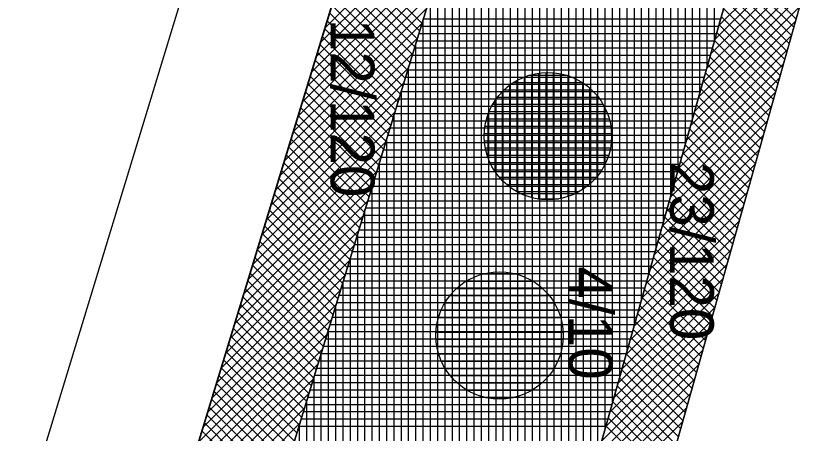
# Model space of a CAD drawing. Extents: x -565346 to -564154, y -1097386 to -1095620.
# Drawn here: x -564251.58 to -564229.82, y -1096486.38 to -1096474.91 of the extents above; entities that cross this region are included whole.
import ezdxf

# ---------------------------------------------------------------- set-up
doc = ezdxf.new("R2010")
doc.units = 0
for name, color, linetype in [('Vrstva 1', 7, 'Continuous'), ('Vrstva 13', 7, 'Continuous'), ('Vrstva 40', 7, 'Continuous'), ('Vrstva 41', 7, 'Continuous'), ('Vrstva 42', 7, 'Continuous'), ('Vrstva 43', 7, 'Continuous'), ('Vrstva 44', 7, 'Continuous')]:
    doc.layers.add(name, color=color, linetype=linetype)

msp = doc.modelspace()

# ---------------------------------------------------------------- linework, layer by layer
at = {"layer": 'Vrstva 1'}
for p, q in [((-564259.14, -1096527.84), (-564234.67, -1096447.65)), ((-564242.07, -1096458.14), (-564259.02, -1096513.75))]:
    msp.add_line(p, q, dxfattribs=at)
at = {"layer": 'Vrstva 13'}
msp.add_line((-564226.29, -1096461.3), (-564238.75, -1096505.56), dxfattribs=at)
at = {"layer": 'Vrstva 41'}
for points in [[(-564230.6, -1096442.93), (-564234.67, -1096447.65), (-564259.14, -1096527.84), (-564264.72, -1096575.85), (-564272.07, -1096706.16), (-564269.623, -1096706.334), (-564262.228, -1096576.061), (-564256.683, -1096528.354)], [(-564221.399, -1096446.296), (-564223.301, -1096445.676), (-564228.215, -1096460.758), (-564240.675, -1096505.018), (-564249.271, -1096529.938), (-564254.757, -1096576.767), (-564262.137, -1096706.758), (-564260.141, -1096706.872), (-564252.76, -1096576.88), (-564247.38, -1096530.59), (-564238.75, -1096505.56), (-564226.29, -1096461.3)]]:
    msp.add_lwpolyline(points, close=True, dxfattribs=at)
at = {"layer": 'Vrstva 42'}
for p, q in [((-564239.31, -1096471.457), (-564243.087, -1096475.234)), ((-564239.435, -1096471.864), (-564243.211, -1096475.641)), ((-564239.559, -1096472.271), (-564243.336, -1096476.048)), ((-564229.383, -1096472.286), (-564232.274, -1096475.177)), ((-564239.683, -1096472.678), (-564243.46, -1096476.455)), ((-564229.494, -1096472.68), (-564232.385, -1096475.571)), ((-564239.808, -1096473.085), (-564243.584, -1096476.862)), ((-564242.434, -1096473.095), (-564240.424, -1096475.105)), ((-564229.604, -1096473.073), (-564232.496, -1096475.965)), ((-564242.501, -1096473.311), (-564240.49, -1096475.322)), ((-564229.715, -1096473.467), (-564232.607, -1096476.358)), ((-564231.769, -1096473.381), (-564230.147, -1096475.002)), ((-564239.932, -1096473.493), (-564243.708, -1096477.269)), ((-564242.567, -1096473.528), (-564240.557, -1096475.538)), ((-564231.831, -1096473.602), (-564230.21, -1096475.223)), ((-564240.056, -1096473.9), (-564243.832, -1096477.676)), ((-564242.633, -1096473.745), (-564240.623, -1096475.755)), ((-564229.826, -1096473.861), (-564232.718, -1096476.752)), ((-564231.893, -1096473.823), (-564230.272, -1096475.444)), ((-564242.699, -1096473.962), (-564240.689, -1096475.972)), ((-564231.955, -1096474.043), (-564230.334, -1096475.664)), ((-564240.18, -1096474.307), (-564243.957, -1096478.083)), ((-564242.765, -1096474.178), (-564240.755, -1096476.188)), ((-564229.937, -1096474.254), (-564232.828, -1096477.146)), ((-564232.017, -1096474.264), (-564230.396, -1096475.885)), ((-564242.831, -1096474.395), (-564240.821, -1096476.405)), ((-564232.079, -1096474.485), (-564230.458, -1096476.106)), ((-564240.305, -1096474.714), (-564244.081, -1096478.49)), ((-564242.897, -1096474.612), (-564240.887, -1096476.622)), ((-564230.048, -1096474.648), (-564232.939, -1096477.54)), ((-564232.141, -1096474.705), (-564230.52, -1096476.327)), ((-564242.964, -1096474.828), (-564240.953, -1096476.838)), ((-564232.204, -1096474.926), (-564230.582, -1096476.547)), ((-564240.429, -1096475.121), (-564244.205, -1096478.897)), ((-564243.03, -1096475.045), (-564241.02, -1096477.055)), ((-564230.158, -1096475.042), (-564233.05, -1096477.933)), ((-564232.266, -1096475.147), (-564230.645, -1096476.768)), ((-564243.096, -1096475.262), (-564241.086, -1096477.272)), ((-564232.328, -1096475.367), (-564230.707, -1096476.989)), ((-564240.553, -1096475.528), (-564244.329, -1096479.304)), ((-564243.162, -1096475.479), (-564241.152, -1096477.489)), ((-564230.269, -1096475.435), (-564233.161, -1096478.327)), ((-564232.39, -1096475.588), (-564230.769, -1096477.209)), ((-564243.228, -1096475.695), (-564241.218, -1096477.705)), ((-564230.38, -1096475.829), (-564233.272, -1096478.721)), ((-564232.452, -1096475.809), (-564230.831, -1096477.43)), ((-564240.678, -1096475.936), (-564244.454, -1096479.711)), ((-564243.294, -1096475.912), (-564241.284, -1096477.922)), ((-564232.514, -1096476.03), (-564230.893, -1096477.651)), ((-564243.36, -1096476.129), (-564241.35, -1096478.139)), ((-564230.491, -1096476.223), (-564233.383, -1096479.114)), ((-564232.576, -1096476.25), (-564230.955, -1096477.872)), ((-564240.802, -1096476.343), (-564244.578, -1096480.118)), ((-564243.426, -1096476.345), (-564241.417, -1096478.355)), ((-564232.639, -1096476.471), (-564231.017, -1096478.092)), ((-564243.493, -1096476.562), (-564241.483, -1096478.572)), ((-564230.602, -1096476.616), (-564233.493, -1096479.508)), ((-564232.701, -1096476.692), (-564231.079, -1096478.313)), ((-564240.926, -1096476.75), (-564244.702, -1096480.525)), ((-564243.559, -1096476.779), (-564241.549, -1096478.789)), ((-564232.763, -1096476.912), (-564231.142, -1096478.534)), ((-564241.051, -1096477.157), (-564244.826, -1096480.932)), ((-564243.625, -1096476.996), (-564241.615, -1096479.005)), ((-564230.713, -1096477.01), (-564233.604, -1096479.902)), ((-564232.825, -1096477.133), (-564231.204, -1096478.754)), ((-564243.691, -1096477.212), (-564241.681, -1096479.222)), ((-564232.887, -1096477.354), (-564231.266, -1096478.975)), ((-564241.175, -1096477.564), (-564244.95, -1096481.339)), ((-564243.757, -1096477.429), (-564241.747, -1096479.439)), ((-564230.823, -1096477.404), (-564233.715, -1096480.295)), ((-564232.949, -1096477.575), (-564231.328, -1096479.196)), ((-564243.823, -1096477.646), (-564241.814, -1096479.655)), ((-564230.934, -1096477.797), (-564233.826, -1096480.689)), ((-564233.011, -1096477.795), (-564231.39, -1096479.416)), ((-564241.299, -1096477.971), (-564245.075, -1096481.747)), ((-564243.889, -1096477.862), (-564241.88, -1096479.872)), ((-564233.073, -1096478.016), (-564231.452, -1096479.637)), ((-564243.955, -1096478.079), (-564241.946, -1096480.089)), ((-564231.045, -1096478.191), (-564233.937, -1096481.083)), ((-564233.136, -1096478.237), (-564231.514, -1096479.858)), ((-564241.424, -1096478.379), (-564245.199, -1096482.154)), ((-564244.022, -1096478.296), (-564242.012, -1096480.305)), ((-564233.198, -1096478.457), (-564231.577, -1096480.079)), ((-564244.088, -1096478.513), (-564242.078, -1096480.522)), ((-564231.156, -1096478.585), (-564234.048, -1096481.476)), ((-564233.26, -1096478.678), (-564231.639, -1096480.299)), ((-564241.548, -1096478.786), (-564245.323, -1096482.561)), ((-564244.154, -1096478.729), (-564242.144, -1096480.739)), ((-564233.322, -1096478.899), (-564231.701, -1096480.52)), ((-564244.22, -1096478.946), (-564242.211, -1096480.955)), ((-564231.267, -1096478.978), (-564234.158, -1096481.87)), ((-564233.384, -1096479.12), (-564231.763, -1096480.741)), ((-564241.672, -1096479.193), (-564245.447, -1096482.968)), ((-564244.286, -1096479.163), (-564242.277, -1096481.172)), ((-564233.446, -1096479.34), (-564231.825, -1096480.961)), ((-564244.352, -1096479.379), (-564242.343, -1096481.389)), ((-564231.378, -1096479.372), (-564234.269, -1096482.264)), ((-564233.508, -1096479.561), (-564231.887, -1096481.182)), ((-564241.797, -1096479.6), (-564245.571, -1096483.375)), ((-564244.418, -1096479.596), (-564242.409, -1096481.605)), ((-564231.488, -1096479.766), (-564234.38, -1096482.657)), ((-564233.571, -1096479.782), (-564231.949, -1096481.403)), ((-564244.484, -1096479.813), (-564242.475, -1096481.822)), ((-564241.921, -1096480.007), (-564245.696, -1096483.782)), ((-564244.551, -1096480.03), (-564242.541, -1096482.039)), ((-564231.599, -1096480.159), (-564234.491, -1096483.051)), ((-564233.633, -1096480.002), (-564232.011, -1096481.624)), ((-564242.045, -1096480.414), (-564245.82, -1096484.189)), ((-564244.617, -1096480.246), (-564242.607, -1096482.256)), ((-564233.695, -1096480.223), (-564232.074, -1096481.844)), ((-564244.683, -1096480.463), (-564242.674, -1096482.472)), ((-564231.71, -1096480.553), (-564234.602, -1096483.445)), ((-564233.757, -1096480.444), (-564232.136, -1096482.065)), ((-564242.17, -1096480.822), (-564245.944, -1096484.596)), ((-564244.749, -1096480.68), (-564242.74, -1096482.689)), ((-564233.819, -1096480.664), (-564232.198, -1096482.286)), ((-564244.815, -1096480.896), (-564242.806, -1096482.906)), ((-564231.821, -1096480.947), (-564234.712, -1096483.838)), ((-564233.881, -1096480.885), (-564232.26, -1096482.506)), ((-564242.294, -1096481.229), (-564246.068, -1096485.003)), ((-564244.881, -1096481.113), (-564242.872, -1096483.122)), ((-564233.943, -1096481.106), (-564232.322, -1096482.727)), ((-564244.947, -1096481.33), (-564242.938, -1096483.339)), ((-564231.932, -1096481.34), (-564234.823, -1096484.232)), ((-564234.005, -1096481.327), (-564232.384, -1096482.948)), ((-564242.418, -1096481.636), (-564246.192, -1096485.41)), ((-564245.014, -1096481.547), (-564243.004, -1096483.556)), ((-564232.043, -1096481.734), (-564234.934, -1096484.626)), ((-564234.068, -1096481.547), (-564232.446, -1096483.169)), ((-564245.08, -1096481.763), (-564243.071, -1096483.772)), ((-564234.13, -1096481.768), (-564232.509, -1096483.389)), ((-564242.543, -1096482.043), (-564246.317, -1096485.817)), ((-564245.146, -1096481.98), (-564243.137, -1096483.989)), ((-564232.153, -1096482.128), (-564235.045, -1096485.019)), ((-564234.192, -1096481.989), (-564232.571, -1096483.61)), ((-564245.212, -1096482.197), (-564243.203, -1096484.206)), ((-564234.254, -1096482.209), (-564232.633, -1096483.831)), ((-564242.667, -1096482.45), (-564246.441, -1096486.224)), ((-564245.278, -1096482.413), (-564243.269, -1096484.422)), ((-564232.264, -1096482.521), (-564235.156, -1096485.413)), ((-564234.316, -1096482.43), (-564232.695, -1096484.051)), ((-564245.344, -1096482.63), (-564243.335, -1096484.639)), ((-564234.378, -1096482.651), (-564232.757, -1096484.272)), ((-564242.791, -1096482.857), (-564246.565, -1096486.631)), ((-564245.41, -1096482.847), (-564243.401, -1096484.856)), ((-564232.375, -1096482.915), (-564235.267, -1096485.807)), ((-564234.44, -1096482.872), (-564232.819, -1096484.493)), ((-564242.916, -1096483.264), (-564246.689, -1096487.038)), ((-564245.476, -1096483.064), (-564243.468, -1096485.072)), ((-564234.503, -1096483.092), (-564232.881, -1096484.713)), ((-564245.543, -1096483.28), (-564243.534, -1096485.289)), ((-564232.486, -1096483.309), (-564235.377, -1096486.2)), ((-564234.565, -1096483.313), (-564232.943, -1096484.934)), ((-564243.04, -1096483.672), (-564246.814, -1096487.445)), ((-564245.609, -1096483.497), (-564243.6, -1096485.506)), ((-564234.627, -1096483.534), (-564233.006, -1096485.155)), ((-564245.675, -1096483.714), (-564243.666, -1096485.722)), ((-564232.597, -1096483.702), (-564235.488, -1096486.594)), ((-564234.689, -1096483.754), (-564233.068, -1096485.376)), ((-564243.164, -1096484.079), (-564246.938, -1096487.852)), ((-564245.741, -1096483.93), (-564243.732, -1096485.939)), ((-564232.707, -1096484.096), (-564235.599, -1096486.988)), ((-564234.751, -1096483.975), (-564233.13, -1096485.596)), ((-564245.807, -1096484.147), (-564243.798, -1096486.156)), ((-564234.813, -1096484.196), (-564233.192, -1096485.817)), ((-564243.289, -1096484.486), (-564247.062, -1096488.259)), ((-564245.873, -1096484.364), (-564243.865, -1096486.372)), ((-564232.818, -1096484.49), (-564235.71, -1096487.381)), ((-564234.875, -1096484.417), (-564233.254, -1096486.038)), ((-564245.939, -1096484.581), (-564243.931, -1096486.589)), ((-564234.937, -1096484.637), (-564233.316, -1096486.258)), ((-564243.413, -1096484.893), (-564247.186, -1096488.666)), ((-564246.005, -1096484.797), (-564243.997, -1096486.806)), ((-564232.929, -1096484.883), (-564235.821, -1096487.775)), ((-564235, -1096484.858), (-564233.378, -1096486.479)), ((-564246.072, -1096485.014), (-564244.063, -1096487.023)), ((-564235.062, -1096485.079), (-564233.441, -1096486.7)), ((-564243.537, -1096485.3), (-564247.31, -1096489.074)), ((-564246.138, -1096485.231), (-564244.129, -1096487.239)), ((-564233.04, -1096485.277), (-564235.932, -1096488.169)), ((-564235.124, -1096485.299), (-564233.503, -1096486.921)), ((-564246.204, -1096485.447), (-564244.195, -1096487.456)), ((-564235.186, -1096485.52), (-564233.565, -1096487.141)), ((-564243.661, -1096485.707), (-564247.435, -1096489.481)), ((-564246.27, -1096485.664), (-564244.262, -1096487.673)), ((-564233.151, -1096485.671), (-564236.042, -1096488.562)), ((-564235.248, -1096485.741), (-564233.627, -1096487.362)), ((-564246.336, -1096485.881), (-564244.328, -1096487.889)), ((-564233.262, -1096486.064), (-564236.153, -1096488.956)), ((-564235.31, -1096485.962), (-564233.689, -1096487.583)), ((-564243.786, -1096486.115), (-564247.559, -1096489.888)), ((-564246.402, -1096486.098), (-564244.394, -1096488.106)), ((-564235.372, -1096486.182), (-564233.751, -1096487.803)), ((-564246.468, -1096486.314), (-564244.46, -1096488.323))]:
    msp.add_line(p, q, dxfattribs=at)
at = {"layer": 'Vrstva 43'}
for p, q in [((-564232.39, -1096475.588), (-564232.39, -1096448.792)), ((-564232.59, -1096476.299), (-564232.59, -1096449.447)), ((-564232.79, -1096477.009), (-564232.79, -1096450.102)), ((-564232.99, -1096477.72), (-564232.99, -1096450.757)), ((-564233.19, -1096478.43), (-564233.19, -1096451.412)), ((-564233.39, -1096479.14), (-564233.39, -1096452.067)), ((-564233.59, -1096479.851), (-564233.59, -1096452.723)), ((-564233.79, -1096480.561), (-564233.79, -1096453.378)), ((-564233.99, -1096481.272), (-564233.99, -1096454.033)), ((-564234.19, -1096481.982), (-564234.19, -1096454.688)), ((-564234.39, -1096482.693), (-564234.39, -1096455.343)), ((-564234.59, -1096483.403), (-564234.59, -1096455.998)), ((-564234.79, -1096484.114), (-564234.79, -1096456.653)), ((-564234.99, -1096484.824), (-564234.99, -1096457.308)), ((-564235.19, -1096485.534), (-564235.19, -1096457.963)), ((-564235.39, -1096486.245), (-564235.39, -1096458.618)), ((-564235.59, -1096486.955), (-564235.59, -1096459.273)), ((-564235.79, -1096487.666), (-564235.79, -1096459.928)), ((-564235.99, -1096488.376), (-564235.99, -1096460.583)), ((-564236.19, -1096489.087), (-564236.19, -1096461.238)), ((-564236.39, -1096489.797), (-564236.39, -1096461.893)), ((-564236.59, -1096490.507), (-564236.59, -1096462.548)), ((-564236.79, -1096491.218), (-564236.79, -1096463.203)), ((-564236.99, -1096491.928), (-564236.99, -1096463.858)), ((-564237.19, -1096492.639), (-564237.19, -1096464.513)), ((-564237.39, -1096493.349), (-564237.39, -1096465.168)), ((-564237.59, -1096494.06), (-564237.59, -1096465.823)), ((-564237.79, -1096494.77), (-564237.79, -1096466.478)), ((-564237.99, -1096495.48), (-564237.99, -1096467.133)), ((-564238.19, -1096496.191), (-564238.19, -1096467.788)), ((-564238.39, -1096496.901), (-564238.39, -1096468.443)), ((-564238.59, -1096497.612), (-564238.59, -1096469.098)), ((-564238.79, -1096498.322), (-564238.79, -1096469.753)), ((-564238.99, -1096499.033), (-564238.99, -1096470.408)), ((-564239.19, -1096499.743), (-564239.19, -1096471.063)), ((-564239.39, -1096500.453), (-564239.39, -1096471.718)), ((-564239.59, -1096501.164), (-564239.59, -1096472.373)), ((-564239.79, -1096501.874), (-564239.79, -1096473.028)), ((-564239.99, -1096502.585), (-564239.99, -1096473.683)), ((-564240.19, -1096503.295), (-564240.19, -1096474.338)), ((-564240.39, -1096504.006), (-564240.39, -1096474.993)), ((-564240.389, -1096474.99), (-564232.222, -1096474.99)), ((-564240.45, -1096475.19), (-564232.278, -1096475.19)), ((-564240.511, -1096475.39), (-564232.334, -1096475.39)), ((-564240.59, -1096504.716), (-564240.59, -1096475.648)), ((-564240.572, -1096475.59), (-564232.39, -1096475.59)), ((-564240.633, -1096475.79), (-564232.447, -1096475.79)), ((-564240.694, -1096475.99), (-564232.503, -1096475.99)), ((-564240.755, -1096476.19), (-564232.559, -1096476.19)), ((-564240.817, -1096476.39), (-564232.616, -1096476.39)), ((-564240.79, -1096505.351), (-564240.79, -1096476.303)), ((-564240.878, -1096476.59), (-564232.672, -1096476.59)), ((-564240.939, -1096476.79), (-564232.728, -1096476.79)), ((-564241, -1096476.99), (-564232.785, -1096476.99)), ((-564240.99, -1096505.931), (-564240.99, -1096476.958)), ((-564241.061, -1096477.19), (-564232.841, -1096477.19)), ((-564241.183, -1096477.59), (-564232.954, -1096477.59)), ((-564241.122, -1096477.39), (-564232.897, -1096477.39)), ((-564241.244, -1096477.79), (-564233.01, -1096477.79)), ((-564241.19, -1096506.511), (-564241.19, -1096477.613)), ((-564241.305, -1096477.99), (-564233.066, -1096477.99)), ((-564241.366, -1096478.19), (-564233.122, -1096478.19)), ((-564241.427, -1096478.39), (-564233.179, -1096478.39)), ((-564241.39, -1096507.091), (-564241.39, -1096478.268)), ((-564241.488, -1096478.59), (-564233.235, -1096478.59)), ((-564241.549, -1096478.79), (-564233.291, -1096478.79)), ((-564241.61, -1096478.99), (-564233.348, -1096478.99)), ((-564241.59, -1096507.671), (-564241.59, -1096478.923)), ((-564241.671, -1096479.19), (-564233.404, -1096479.19)), ((-564241.733, -1096479.39), (-564233.46, -1096479.39)), ((-564241.794, -1096479.59), (-564233.517, -1096479.59)), ((-564241.79, -1096508.25), (-564241.79, -1096479.578)), ((-564241.916, -1096479.99), (-564233.629, -1096479.99)), ((-564241.855, -1096479.79), (-564233.573, -1096479.79)), ((-564241.977, -1096480.19), (-564233.685, -1096480.19)), ((-564242.038, -1096480.39), (-564233.742, -1096480.39)), ((-564241.99, -1096508.83), (-564241.99, -1096480.233)), ((-564242.099, -1096480.59), (-564233.798, -1096480.59)), ((-564242.16, -1096480.79), (-564233.854, -1096480.79)), ((-564242.221, -1096480.99), (-564233.911, -1096480.99)), ((-564242.19, -1096509.41), (-564242.19, -1096480.888)), ((-564242.282, -1096481.19), (-564233.967, -1096481.19)), ((-564242.343, -1096481.39), (-564234.023, -1096481.39)), ((-564242.404, -1096481.59), (-564234.08, -1096481.59)), ((-564242.39, -1096509.99), (-564242.39, -1096481.543)), ((-564242.465, -1096481.79), (-564234.136, -1096481.79)), ((-564242.526, -1096481.99), (-564234.192, -1096481.99)), ((-564242.649, -1096482.39), (-564234.305, -1096482.39)), ((-564242.59, -1096510.57), (-564242.59, -1096482.198)), ((-564242.587, -1096482.19), (-564234.248, -1096482.19)), ((-564242.71, -1096482.59), (-564234.361, -1096482.59)), ((-564242.771, -1096482.79), (-564234.417, -1096482.79)), ((-564242.832, -1096482.99), (-564234.474, -1096482.99)), ((-564242.79, -1096511.149), (-564242.79, -1096482.853)), ((-564242.893, -1096483.19), (-564234.53, -1096483.19)), ((-564242.954, -1096483.39), (-564234.586, -1096483.39)), ((-564243.015, -1096483.59), (-564234.643, -1096483.59)), ((-564242.99, -1096511.729), (-564242.99, -1096483.508)), ((-564243.076, -1096483.79), (-564234.699, -1096483.79)), ((-564243.137, -1096483.99), (-564234.755, -1096483.99)), ((-564243.198, -1096484.19), (-564234.812, -1096484.19)), ((-564243.19, -1096512.309), (-564243.19, -1096484.163)), ((-564243.259, -1096484.39), (-564234.868, -1096484.39)), ((-564243.32, -1096484.59), (-564234.924, -1096484.59)), ((-564243.442, -1096484.99), (-564235.037, -1096484.99)), ((-564243.39, -1096512.889), (-564243.39, -1096484.818)), ((-564243.381, -1096484.79), (-564234.98, -1096484.79)), ((-564243.503, -1096485.19), (-564235.093, -1096485.19)), ((-564243.565, -1096485.39), (-564235.149, -1096485.39)), ((-564243.626, -1096485.59), (-564235.206, -1096485.59)), ((-564243.59, -1096513.469), (-564243.59, -1096485.473)), ((-564243.687, -1096485.79), (-564235.262, -1096485.79)), ((-564243.748, -1096485.99), (-564235.318, -1096485.99)), ((-564243.809, -1096486.19), (-564235.375, -1096486.19)), ((-564243.79, -1096514.048), (-564243.79, -1096486.128))]:
    msp.add_line(p, q, dxfattribs=at)
msp.add_lwpolyline([(-564261.274, -1096726.84), (-564260.141, -1096706.872), (-564262.137, -1096706.758), (-564254.757, -1096576.767), (-564249.271, -1096529.938), (-564240.675, -1096505.018), (-564228.215, -1096460.758), (-564223.301, -1096445.676), (-564221.399, -1096446.296), (-564218.92, -1096438.69), (-564229.82, -1096442.05), (-564230.6, -1096442.93), (-564256.683, -1096528.354), (-564262.228, -1096576.061), (-564269.623, -1096706.334), (-564272.07, -1096706.16), (-564273.28, -1096725.96)], dxfattribs=at)
at = {"layer": 'Vrstva 44'}
for p, q in [((-564237.21, -1096479.945), (-564237.21, -1096476.483)), ((-564237.01, -1096479.963), (-564237.01, -1096476.467)), ((-564236.81, -1096479.956), (-564236.81, -1096476.472)), ((-564236.61, -1096479.926), (-564236.61, -1096476.5)), ((-564237.81, -1096479.744), (-564237.81, -1096476.684)), ((-564237.61, -1096479.84), (-564237.61, -1096476.588)), ((-564237.47, -1096476.54), (-564236.456, -1096476.54)), ((-564237.41, -1096479.905), (-564237.41, -1096476.523)), ((-564236.41, -1096479.872), (-564236.41, -1096476.556)), ((-564236.21, -1096479.793), (-564236.21, -1096476.637)), ((-564238.163, -1096476.94), (-564235.767, -1096476.94)), ((-564238.01, -1096479.615), (-564238.01, -1096476.812)), ((-564237.906, -1096476.74), (-564236.023, -1096476.74)), ((-564236.01, -1096479.679), (-564236.01, -1096476.748)), ((-564235.81, -1096479.528), (-564235.81, -1096476.901)), ((-564238.344, -1096477.14), (-564235.585, -1096477.14)), ((-564238.21, -1096479.441), (-564238.21, -1096476.988)), ((-564235.61, -1096479.319), (-564235.61, -1096477.107)), ((-564238.479, -1096477.34), (-564235.45, -1096477.34)), ((-564238.41, -1096479.198), (-564238.41, -1096477.231)), ((-564238.577, -1096477.54), (-564235.35, -1096477.54)), ((-564235.41, -1096479.015), (-564235.41, -1096477.413)), ((-564238.647, -1096477.74), (-564235.282, -1096477.74)), ((-564238.61, -1096478.805), (-564238.61, -1096477.62)), ((-564238.692, -1096477.94), (-564235.238, -1096477.94)), ((-564238.712, -1096478.14), (-564235.217, -1096478.14)), ((-564238.708, -1096478.34), (-564235.219, -1096478.34)), ((-564238.682, -1096478.54), (-564235.246, -1096478.54)), ((-564238.632, -1096478.74), (-564235.297, -1096478.74)), ((-564238.556, -1096478.94), (-564235.373, -1096478.94)), ((-564238.447, -1096479.14), (-564235.48, -1096479.14)), ((-564238.303, -1096479.34), (-564235.627, -1096479.34)), ((-564238.103, -1096479.54), (-564235.825, -1096479.54)), ((-564237.817, -1096479.74), (-564236.111, -1096479.74)), ((-564237.242, -1096479.94), (-564236.676, -1096479.94)), ((-564238.39, -1096485.44), (-564238.39, -1096481.948)), ((-564238.19, -1096485.44), (-564238.19, -1096481.949)), ((-564238.99, -1096485.298), (-564238.99, -1096482.09)), ((-564238.79, -1096485.372), (-564238.79, -1096482.017)), ((-564238.728, -1096482), (-564237.863, -1096482)), ((-564238.59, -1096485.417), (-564238.59, -1096481.97)), ((-564237.99, -1096485.416), (-564237.99, -1096481.972)), ((-564237.79, -1096485.368), (-564237.79, -1096482.019)), ((-564237.59, -1096485.294), (-564237.59, -1096482.093)), ((-564239.39, -1096485.058), (-564239.39, -1096482.331)), ((-564239.204, -1096482.2), (-564237.387, -1096482.2)), ((-564239.19, -1096485.195), (-564239.19, -1096482.192)), ((-564237.39, -1096485.192), (-564237.39, -1096482.198)), ((-564237.19, -1096485.049), (-564237.19, -1096482.336)), ((-564239.658, -1096482.6), (-564236.93, -1096482.6)), ((-564239.59, -1096484.868), (-564239.59, -1096482.519)), ((-564239.471, -1096482.4), (-564237.119, -1096482.4)), ((-564236.99, -1096484.86), (-564236.99, -1096482.53)), ((-564239.798, -1096482.8), (-564236.792, -1096482.8)), ((-564239.79, -1096484.599), (-564239.79, -1096482.787)), ((-564236.79, -1096484.587), (-564236.79, -1096482.803)), ((-564239.899, -1096483), (-564236.688, -1096483)), ((-564239.99, -1096484.122), (-564239.99, -1096483.263)), ((-564239.971, -1096483.2), (-564236.617, -1096483.2)), ((-564240.018, -1096483.4), (-564236.571, -1096483.4)), ((-564236.59, -1096484.084), (-564236.59, -1096483.299)), ((-564240.042, -1096483.6), (-564236.548, -1096483.6)), ((-564240.04, -1096483.8), (-564236.548, -1096483.8)), ((-564240.015, -1096484), (-564236.572, -1096484)), ((-564239.968, -1096484.2), (-564236.621, -1096484.2)), ((-564239.895, -1096484.4), (-564236.695, -1096484.4)), ((-564239.79, -1096484.6), (-564236.797, -1096484.6)), ((-564239.648, -1096484.8), (-564236.941, -1096484.8)), ((-564239.456, -1096485), (-564237.13, -1096485)), ((-564239.182, -1096485.2), (-564237.405, -1096485.2)), ((-564238.683, -1096485.4), (-564237.913, -1096485.4))]:
    msp.add_line(p, q, dxfattribs=at)
for centre in [(-564236.964, -1096478.214), (-564238.294, -1096483.694)]:
    msp.add_circle(centre, 1.75, dxfattribs=at)

# ---------------------------------------------------------------- texts
at = {"layer": 'Vrstva 40'}
for s, p in [('12/120', (-564242.93, -1096474.99)), ('23/120', (-564233.61, -1096478.92)), ('4/10', (-564236.39, -1096481.79))]:
    msp.add_text(s, height=1.2, rotation=270, dxfattribs=at).set_placement(p)

doc.saveas('drawing.dxf')
